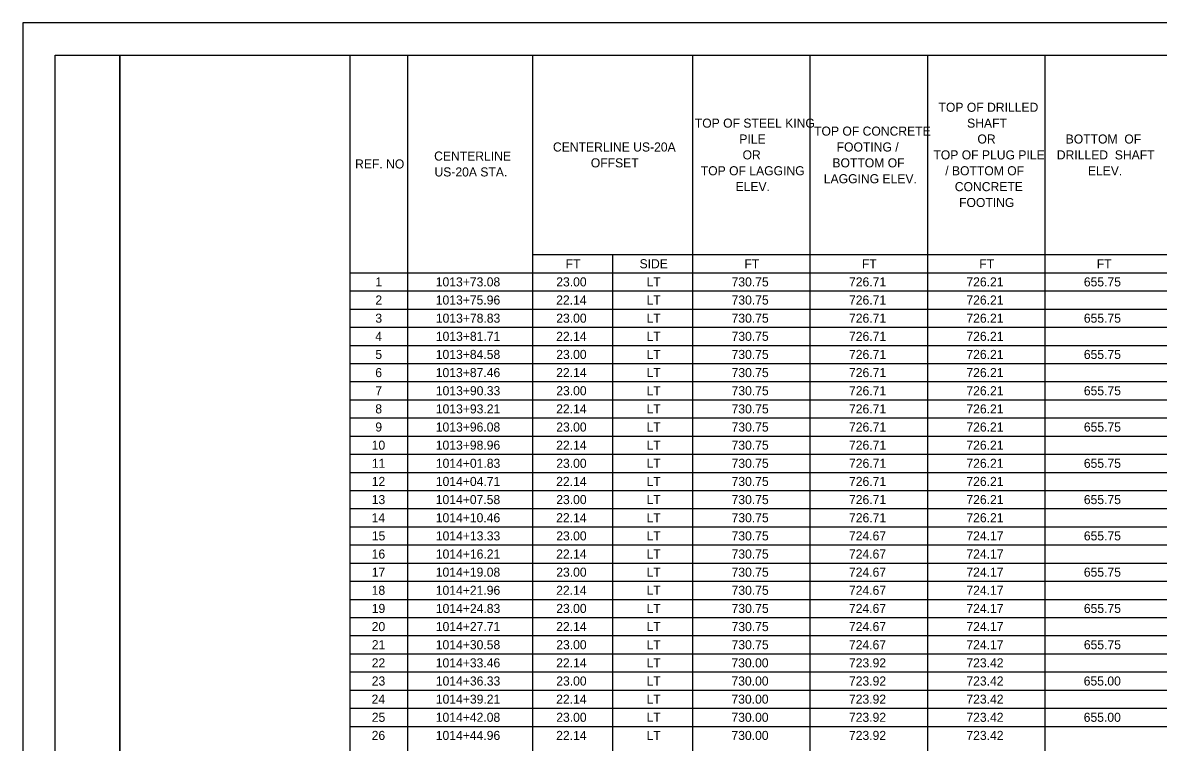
# Model space of a CAD drawing. Extents: x 0 to 34, y 0 to 22.
# Drawn here: x 0 to 17.52, y 10.89 to 22 of the extents above; entities that cross this region are included whole.
import ezdxf

# ---------------------------------------------------------------- set-up
doc = ezdxf.new("R2010")
doc.units = 0
for name, color, linetype in [('SH_Border', 7, 'Continuous'), ('SH_Cut_Line', 7, 'Continuous'), ('SH_Data', 7, 'Continuous'), ('SH_Text', 7, 'Continuous')]:
    doc.layers.add(name, color=color, linetype=linetype)

msp = doc.modelspace()

# ---------------------------------------------------------------- linework, layer by layer
at = {"layer": 'SH_Border'}
for points in [[(0.5, 21.5), (1.5, 21.5), (1.5, 0.5), (0.5, 0.5)], [(1.5, 21.5), (33.5, 21.5), (33.5, 0.5), (1.5, 0.5)]]:
    msp.add_lwpolyline(points, close=True, dxfattribs=at)
at = {"layer": 'SH_Cut_Line'}
msp.add_lwpolyline([(0, 0), (34, 0), (34, 22), (0, 22)], close=True, dxfattribs=at)
at = {"layer": 'SH_Data'}
for p, q in [((5.048, 21.5), (28.452, 21.5)), ((5.048, 21.5), (5.048, 0.5)), ((5.937, 21.5), (5.937, 1.06)), ((7.864, 21.5), (7.864, 1.06)), ((10.335, 21.5), (10.335, 1.06)), ((12.146, 21.5), (12.146, 1.06)), ((13.958, 21.5), (13.958, 1.06)), ((15.77, 21.5), (15.77, 1.06)), ((7.864, 18.42), (28.452, 18.42)), ((9.099, 18.42), (9.099, 1.06)), ((5.048, 18.14), (28.452, 18.14)), ((5.048, 17.86), (28.452, 17.86)), ((5.048, 17.58), (28.452, 17.58)), ((5.048, 17.3), (28.452, 17.3)), ((5.048, 17.02), (28.452, 17.02)), ((5.048, 16.74), (28.452, 16.74)), ((5.048, 16.46), (28.452, 16.46)), ((5.048, 16.18), (28.452, 16.18)), ((5.048, 15.9), (28.452, 15.9)), ((5.048, 15.62), (28.452, 15.62)), ((5.048, 15.34), (28.452, 15.34)), ((5.048, 15.06), (28.452, 15.06)), ((5.048, 14.78), (28.452, 14.78)), ((5.048, 14.5), (28.452, 14.5)), ((5.048, 14.22), (28.452, 14.22)), ((5.048, 13.94), (28.452, 13.94)), ((5.048, 13.66), (28.452, 13.66)), ((5.048, 13.38), (28.452, 13.38)), ((5.048, 13.1), (28.452, 13.1)), ((5.048, 12.82), (28.452, 12.82)), ((5.048, 12.54), (28.452, 12.54)), ((5.048, 12.26), (28.452, 12.26)), ((5.048, 11.98), (28.452, 11.98)), ((5.048, 11.7), (28.452, 11.7)), ((5.048, 11.42), (28.452, 11.42)), ((5.048, 11.14), (28.452, 11.14))]:
    msp.add_line(p, q, dxfattribs=at)

# ---------------------------------------------------------------- texts
at = {"layer": 'SH_Text'}
for s, p in [('TOP OF DRILLED ', (14.13, 20.625)), ('TOP OF STEEL KING ', (10.37, 20.38)), ('SHAFT', (14.571, 20.38)), ('TOP OF CONCRETE ', (12.21, 20.257)), ('CENTERLINE US-20A ', (8.181, 20.012)), ('PILE ', (11.057, 20.135)), ('FOOTING / ', (12.558, 20.012)), ('OR', (14.73, 20.135)), ('BOTTOM  OF  ', (16.092, 20.135)), ('CENTERLINE ', (6.348, 19.872)), ('OR', (11.107, 19.89)), ('TOP OF PLUG PILE ', (14.051, 19.89)), ('DRILLED  SHAFT  ', (15.955, 19.89)), ('REF. NO', (5.128, 19.75)), ('OFFSET', (8.765, 19.767)), ('BOTTOM OF ', (12.493, 19.767)), ('US-20A STA.', (6.353, 19.627)), ('TOP OF LAGGING ', (10.462, 19.645)), ('LAGGING ELEV.', (12.36, 19.522)), ('/ BOTTOM OF ', (14.233, 19.645)), ('ELEV.', (16.434, 19.645)), ('ELEV.', (10.998, 19.4)), ('CONCRETE ', (14.381, 19.4)), ('FOOTING', (14.447, 19.155)), ('FT', (8.377, 18.21)), ('SIDE', (9.517, 18.21)), ('FT', (11.136, 18.21)), ('FT', (12.948, 18.21)), ('FT', (14.76, 18.21)), ('FT', (16.571, 18.21)), ('1', (5.441, 17.93)), ('1013+73.08', (6.373, 17.93)), ('23.00', (8.232, 17.93)), ('LT', (9.625, 17.93)), ('730.75', (10.937, 17.93)), ('726.71', (12.749, 17.93)), ('726.21', (14.56, 17.93)), ('655.75', (16.372, 17.93)), ('2', (5.441, 17.65)), ('1013+75.96', (6.373, 17.65)), ('22.14', (8.231, 17.65)), ('LT', (9.625, 17.65)), ('730.75', (10.937, 17.65)), ('726.71', (12.749, 17.65)), ('726.21', (14.56, 17.65)), ('3', (5.441, 17.37)), ('1013+78.83', (6.374, 17.37)), ('23.00', (8.232, 17.37)), ('LT', (9.625, 17.37)), ('730.75', (10.937, 17.37)), ('726.71', (12.749, 17.37)), ('726.21', (14.56, 17.37)), ('655.75', (16.372, 17.37)), ('4', (5.439, 17.09)), ('1013+81.71', (6.374, 17.09)), ('22.14', (8.231, 17.09)), ('LT', (9.625, 17.09)), ('730.75', (10.937, 17.09)), ('726.71', (12.749, 17.09)), ('726.21', (14.56, 17.09)), ('5', (5.441, 16.81)), ('1013+84.58', (6.373, 16.81)), ('23.00', (8.232, 16.81)), ('LT', (9.625, 16.81)), ('730.75', (10.937, 16.81)), ('726.71', (12.749, 16.81)), ('726.21', (14.56, 16.81)), ('655.75', (16.372, 16.81)), ('6', (5.44, 16.53)), ('1013+87.46', (6.373, 16.53)), ('22.14', (8.231, 16.53)), ('LT', (9.625, 16.53)), ('730.75', (10.937, 16.53)), ('726.71', (12.749, 16.53)), ('726.21', (14.56, 16.53)), ('7', (5.441, 16.25)), ('1013+90.33', (6.374, 16.25)), ('23.00', (8.232, 16.25)), ('LT', (9.625, 16.25)), ('730.75', (10.937, 16.25)), ('726.71', (12.749, 16.25)), ('726.21', (14.56, 16.25)), ('655.75', (16.372, 16.25)), ('8', (5.44, 15.97)), ('1013+93.21', (6.374, 15.97)), ('22.14', (8.231, 15.97)), ('LT', (9.625, 15.97)), ('730.75', (10.937, 15.97)), ('726.71', (12.749, 15.97)), ('726.21', (14.56, 15.97)), ('9', (5.441, 15.69)), ('1013+96.08', (6.373, 15.69)), ('23.00', (8.232, 15.69)), ('LT', (9.625, 15.69)), ('730.75', (10.937, 15.69)), ('726.71', (12.749, 15.69)), ('726.21', (14.56, 15.69)), ('655.75', (16.372, 15.69)), ('10', (5.384, 15.41)), ('1013+98.96', (6.373, 15.41)), ('22.14', (8.231, 15.41)), ('LT', (9.625, 15.41)), ('730.75', (10.937, 15.41)), ('726.71', (12.749, 15.41)), ('726.21', (14.56, 15.41)), ('11', (5.386, 15.13)), ('1014+01.83', (6.374, 15.13)), ('23.00', (8.232, 15.13)), ('LT', (9.625, 15.13)), ('730.75', (10.937, 15.13)), ('726.71', (12.749, 15.13)), ('726.21', (14.56, 15.13)), ('655.75', (16.372, 15.13)), ('12', (5.385, 14.85)), ('1014+04.71', (6.374, 14.85)), ('22.14', (8.231, 14.85)), ('LT', (9.625, 14.85)), ('730.75', (10.937, 14.85)), ('726.71', (12.749, 14.85)), ('726.21', (14.56, 14.85)), ('13', (5.385, 14.57)), ('1014+07.58', (6.373, 14.57)), ('23.00', (8.232, 14.57)), ('LT', (9.625, 14.57)), ('730.75', (10.937, 14.57)), ('726.71', (12.749, 14.57)), ('726.21', (14.56, 14.57)), ('655.75', (16.372, 14.57)), ('14', (5.383, 14.29)), ('1014+10.46', (6.373, 14.29)), ('22.14', (8.231, 14.29)), ('LT', (9.625, 14.29)), ('730.75', (10.937, 14.29)), ('726.71', (12.749, 14.29)), ('726.21', (14.56, 14.29)), ('15', (5.386, 14.01)), ('1014+13.33', (6.374, 14.01)), ('23.00', (8.232, 14.01)), ('LT', (9.625, 14.01)), ('730.75', (10.937, 14.01)), ('724.67', (12.748, 14.01)), ('724.17', (14.56, 14.01)), ('655.75', (16.372, 14.01)), ('16', (5.384, 13.73)), ('1014+16.21', (6.374, 13.73)), ('22.14', (8.231, 13.73)), ('LT', (9.625, 13.73)), ('730.75', (10.937, 13.73)), ('724.67', (12.748, 13.73)), ('724.17', (14.56, 13.73)), ('17', (5.385, 13.45)), ('1014+19.08', (6.373, 13.45)), ('23.00', (8.232, 13.45)), ('LT', (9.625, 13.45)), ('730.75', (10.937, 13.45)), ('724.67', (12.748, 13.45)), ('724.17', (14.56, 13.45)), ('655.75', (16.372, 13.45)), ('18', (5.384, 13.17)), ('1014+21.96', (6.373, 13.17)), ('22.14', (8.231, 13.17)), ('LT', (9.625, 13.17)), ('730.75', (10.937, 13.17)), ('724.67', (12.748, 13.17)), ('724.17', (14.56, 13.17)), ('19', (5.385, 12.89)), ('1014+24.83', (6.374, 12.89)), ('23.00', (8.232, 12.89)), ('LT', (9.625, 12.89)), ('730.75', (10.937, 12.89)), ('724.67', (12.748, 12.89)), ('724.17', (14.56, 12.89)), ('655.75', (16.372, 12.89)), ('20', (5.384, 12.61)), ('1014+27.71', (6.374, 12.61)), ('22.14', (8.231, 12.61)), ('LT', (9.625, 12.61)), ('730.75', (10.937, 12.61)), ('724.67', (12.748, 12.61)), ('724.17', (14.56, 12.61)), ('21', (5.386, 12.33)), ('1014+30.58', (6.373, 12.33)), ('23.00', (8.232, 12.33)), ('LT', (9.625, 12.33)), ('730.75', (10.937, 12.33)), ('724.67', (12.748, 12.33)), ('724.17', (14.56, 12.33)), ('655.75', (16.372, 12.33)), ('22', (5.385, 12.05)), ('1014+33.46', (6.373, 12.05)), ('22.14', (8.231, 12.05)), ('LT', (9.625, 12.05)), ('730.00', (10.935, 12.05)), ('723.92', (12.748, 12.05)), ('723.42', (14.56, 12.05)), ('23', (5.385, 11.77)), ('1014+36.33', (6.374, 11.77)), ('23.00', (8.232, 11.77)), ('LT', (9.625, 11.77)), ('730.00', (10.935, 11.77)), ('723.92', (12.748, 11.77)), ('723.42', (14.56, 11.77)), ('655.00', (16.37, 11.77)), ('24', (5.383, 11.49)), ('1014+39.21', (6.374, 11.49)), ('22.14', (8.231, 11.49)), ('LT', (9.625, 11.49)), ('730.00', (10.935, 11.49)), ('723.92', (12.748, 11.49)), ('723.42', (14.56, 11.49)), ('25', (5.386, 11.21)), ('1014+42.08', (6.373, 11.21)), ('23.00', (8.232, 11.21)), ('LT', (9.625, 11.21)), ('730.00', (10.935, 11.21)), ('723.92', (12.748, 11.21)), ('723.42', (14.56, 11.21)), ('655.00', (16.37, 11.21)), ('26', (5.384, 10.93)), ('1014+44.96', (6.373, 10.93)), ('22.14', (8.231, 10.93)), ('LT', (9.625, 10.93)), ('730.00', (10.935, 10.93)), ('723.92', (12.748, 10.93)), ('723.42', (14.56, 10.93))]:
    msp.add_text(s, height=0.14, dxfattribs=at).set_placement(p)

doc.saveas('drawing.dxf')
